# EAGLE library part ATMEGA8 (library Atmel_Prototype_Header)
IC AVR MCU 8K LV 8MHZ IND 32TQFP , Atmel Part number ATMEGA8L-8AI
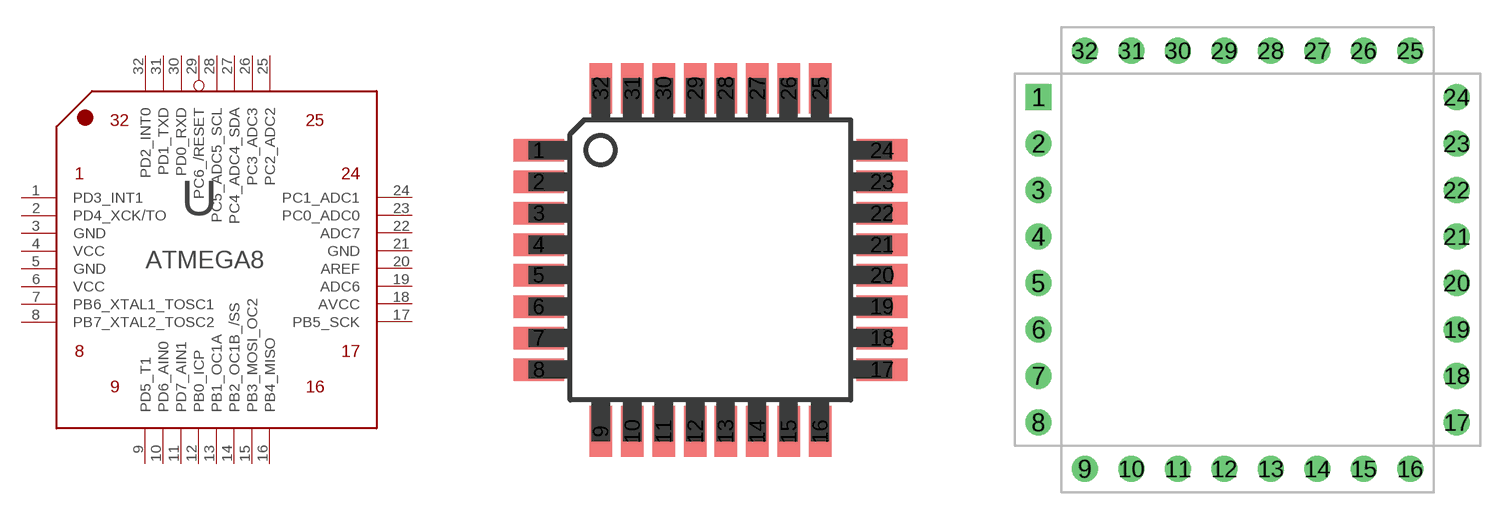
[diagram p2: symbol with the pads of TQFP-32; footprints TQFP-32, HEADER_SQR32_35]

Designator prefix U

## ATMEGA8_TQFP  [TQFP-32]
1  PD3_INT1
2  PD4_XCK/TO
3  GND  pwr
4  VCC  pwr
5  GND  pwr
6  VCC  pwr
7  PB6_XTAL1_TOSC1
8  PB7_XTAL2_TOSC2
9  PD5_T1
10  PD6_AIN0
11  PD7_AIN1
12  PB0_ICP
13  PB1_OC1A
14  PB2_OC1B_/SS
15  PB3_MOSI_OC2
16  PB4_MISO
17  PB5_SCK
18  AVCC  pwr
19  ADC6  pwr
20  AREF  pwr
21  GND  pwr
22  ADC7
23  PC0_ADC0
24  PC1_ADC1
25  PC2_ADC2
26  PC3_ADC3
27  PC4_ADC4_SDA
28  PC5_ADC5_SCL
29  PC6_/RESET
30  PD0_RXD
31  PD1_TXD
32  PD2_INT0

## ATMEGA8_SINGLE_35  [HEADER_SQR32_35]
Pads as for TQFP-32

## ATMEGA8_SINGLE_43  [HEADER_SQR32_43]
Pads as for TQFP-32

## ATMEGA8_DIL_32  [DIL32]
Pads as for TQFP-32

## Footprint TQFP-32 (pad centres in mm)
smd 1.27 x 0.559: 1 -4.293,2.743; 2 -4.293,1.956; 3 -4.293,1.168; 4 -4.293,0.381; 5 -4.293,-0.381; 6 -4.293,-1.168; 7 -4.293,-1.956; 8 -4.293,-2.743; 17 4.293,-2.743; 18 4.293,-1.956; 19 4.293,-1.168; 20 4.293,-0.381; 21 4.293,0.381; 22 4.293,1.168; 23 4.293,1.956; 24 4.293,2.743
smd 0.559 x 1.27: 9 -2.743,-4.293; 10 -1.956,-4.293; 11 -1.168,-4.293; 12 -0.381,-4.293; 13 0.381,-4.293; 14 1.168,-4.293; 15 1.956,-4.293; 16 2.743,-4.293; 25 2.743,4.293; 26 1.956,4.293; 27 1.168,4.293; 28 0.381,4.293; 29 -0.381,4.293; 30 -1.168,4.293; 31 -1.956,4.293; 32 -2.743,4.293

## Footprint HEADER_SQR32_35 (pad centres in mm)
drill 0.9 square: 1 -11.43,8.89
drill 0.9 round: 2 -11.43,6.35; 3 -11.43,3.81; 4 -11.43,1.27; 5 -11.43,-1.27; 6 -11.43,-3.81; 7 -11.43,-6.35; 8 -11.43,-8.89; 9 -8.89,-11.43; 10 -6.35,-11.43; 11 -3.81,-11.43; 12 -1.27,-11.43; 13 1.27,-11.43; 14 3.81,-11.43; 15 6.35,-11.43; 16 8.89,-11.43; 17 11.43,-8.89; 18 11.43,-6.35; 19 11.43,-3.81; 20 11.43,-1.27; 21 11.43,1.27; 22 11.43,3.81; 23 11.43,6.35; 24 11.43,8.89; 25 8.89,11.43; 26 6.35,11.43; 27 3.81,11.43; 28 1.27,11.43; 29 -1.27,11.43; 30 -3.81,11.43; 31 -6.35,11.43; 32 -8.89,11.43

## Footprint HEADER_SQR32_43 (pad centres in mm)
drill 1.1 square: 1 -11.43,8.89
drill 1.1 round: 2 -11.43,6.35; 3 -11.43,3.81; 4 -11.43,1.27; 5 -11.43,-1.27; 6 -11.43,-3.81; 7 -11.43,-6.35; 8 -11.43,-8.89; 9 -8.89,-11.43; 10 -6.35,-11.43; 11 -3.81,-11.43; 12 -1.27,-11.43; 13 1.27,-11.43; 14 3.81,-11.43; 15 6.35,-11.43; 16 8.89,-11.43; 17 11.43,-8.89; 18 11.43,-6.35; 19 11.43,-3.81; 20 11.43,-1.27; 21 11.43,1.27; 22 11.43,3.81; 23 11.43,6.35; 24 11.43,8.89; 25 8.89,11.43; 26 6.35,11.43; 27 3.81,11.43; 28 1.27,11.43; 29 -1.27,11.43; 30 -3.81,11.43; 31 -6.35,11.43; 32 -8.89,11.43

## Footprint DIL32 (pad centres in mm)
Dual In Line
drill 0.813 long: 1 -19.05,-7.62; 2 -16.51,-7.62; 3 -13.97,-7.62; 4 -11.43,-7.62; 5 -8.89,-7.62; 6 -6.35,-7.62; 7 -3.81,-7.62; 8 -1.27,-7.62; 9 1.27,-7.62; 10 3.81,-7.62; 11 6.35,-7.62; 12 8.89,-7.62; 13 11.43,-7.62; 14 13.97,-7.62; 15 16.51,-7.62; 16 19.05,-7.62; 17 19.05,7.62; 18 16.51,7.62; 19 13.97,7.62; 20 11.43,7.62; 21 8.89,7.62; 22 6.35,7.62; 23 3.81,7.62; 24 1.27,7.62; 25 -1.27,7.62; 26 -3.81,7.62; 27 -6.35,7.62; 28 -8.89,7.62; 29 -11.43,7.62; 30 -13.97,7.62; 31 -16.51,7.62; 32 -19.05,7.62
